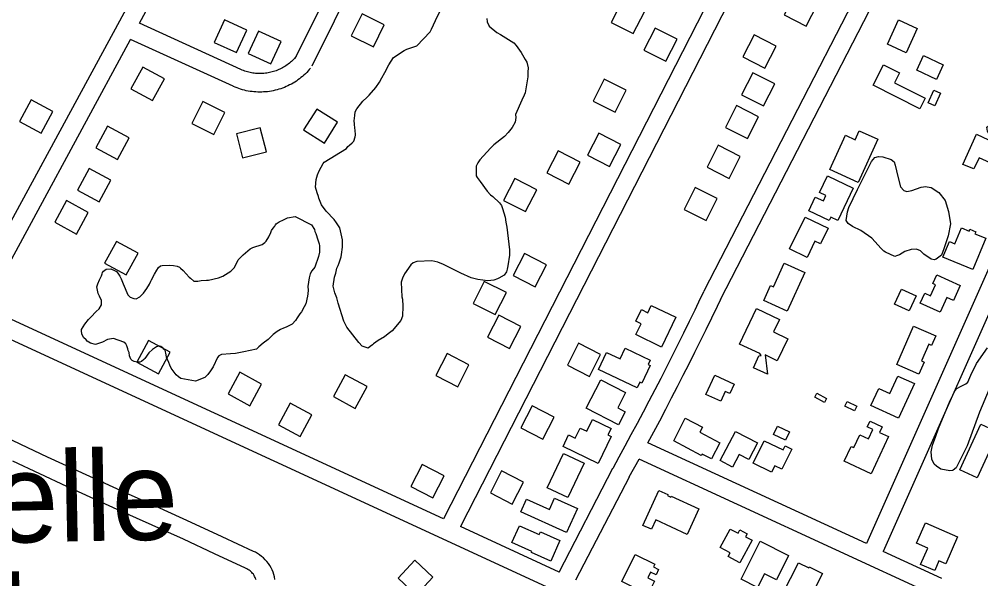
# Model space of a CAD drawing. Extents: x 3683402 to 3721514, y 487807 to 513565.
# Drawn here: x 3705384 to 3706941, y 494703 to 495610 of the extents above; entities that cross this region are included whole.
import ezdxf

# ---------------------------------------------------------------- set-up
doc = ezdxf.new("R2010")
doc.units = 0
for name, color, linetype in [('V-BLDG-OTLN', 7, 'Continuous'), ('V-ROAD-CNTR', 7, 'Continuous'), ('V-SITE-VEGE', 7, 'Continuous'), ('V-TOPO-GNAM-IDEN', 7, 'Continuous')]:
    doc.layers.add(name, color=color, linetype=linetype)

msp = doc.modelspace()

# ---------------------------------------------------------------- linework, layer by layer
at = {"layer": 'V-BLDG-OTLN'}
for points in [[(3706378.4, 495586.3), (3706396.6, 495621.9), (3706361, 495640.1), (3706342.8, 495604.5)], [(3706658.5, 495598.4), (3706676.6, 495634.1), (3706641, 495652.2), (3706622.8, 495616.6)], [(3705699.6, 495572.2), (3705736, 495555.6), (3705752.6, 495591.9), (3705716.3, 495608.6)], [(3705939.4, 495618.6), (3705921.6, 495582.7), (3705957.5, 495565), (3705975.2, 495600.8)], [(3706838.3, 495594.8), (3706820.2, 495555.3), (3706790, 495569.1), (3706808.1, 495608.6)], [(3706431.1, 495541.6), (3706449.3, 495577.2), (3706413.7, 495595.4), (3706395.5, 495559.8)], [(3705755, 495553.9), (3705791.4, 495537.3), (3705808, 495573.7), (3705771.7, 495590.3)], [(3706591.5, 495530.6), (3706609.7, 495566.3), (3706574, 495584.4), (3706555.9, 495548.7)], [(3706837.6, 495527.1), (3706848.6, 495550.8), (3706880.6, 495535.9), (3706869.6, 495512.2)], [(3705584, 495532.2), (3705564.9, 495497), (3705600.1, 495477.9), (3705619.2, 495513.1)], [(3706801.5, 495506.8), (3706851.1, 495481.7), (3706842.5, 495464.7), (3706767.1, 495502.8), (3706783.8, 495535.8), (3706809.5, 495522.7)], [(3706589.4, 495469.1), (3706607.6, 495504.8), (3706571.9, 495522.9), (3706553.8, 495487.3)], [(3706348.9, 495458.9), (3706367.1, 495494.5), (3706331.5, 495512.7), (3706313.3, 495477.1)], [(3706856.1, 495474), (3706865.3, 495494.5), (3706875.9, 495489.7), (3706866.7, 495469.3)], [(3705419.4, 495424.9), (3705438.5, 495460), (3705403.3, 495479.1), (3705384.3, 495443.9)], [(3705663.5, 495440.5), (3705699.4, 495422.8), (3705717.1, 495458.6), (3705681.3, 495476.3)], [(3706563.4, 495416.2), (3706581.5, 495451.8), (3706545.9, 495470), (3706527.7, 495434.3)], [(3705878.3, 495408.9), (3705899.7, 495442.7), (3705865.9, 495464.1), (3705844.5, 495430.3)], [(3706912, 495374.5), (3706934.3, 495423.2), (3706953.9, 495414.2), (3706958.1, 495423.2), (3706955.1, 495423.9), (3706952.1, 495428.2), (3706951.2, 495434.8), (3706956.3, 495439.1), (3706962.9, 495439), (3706964.2, 495438.2), (3706976.5, 495466.2), (3707016.6, 495448.1), (3706991.5, 495396.4), (3706982.1, 495400.9), (3706969.3, 495371.1), (3706938.5, 495385.3), (3706929.9, 495367.1)], [(3705526.9, 495436.4), (3705507.8, 495401.3), (3705542.9, 495382.2), (3705562, 495417.3)], [(3705745.5, 495385), (3705784.3, 495394.9), (3705774.4, 495433.6), (3705735.7, 495423.8)], [(3706340.2, 495371.1), (3706358.4, 495406.7), (3706322.8, 495424.9), (3706304.6, 495389.3)], [(3706696.9, 495366), (3706722.1, 495421.7), (3706738, 495414.5), (3706744.5, 495428.8), (3706774.4, 495415.3), (3706742.8, 495345.3)], [(3706274.1, 495342.3), (3706292.3, 495378), (3706256.7, 495396.2), (3706238.5, 495360.6)], [(3706533.7, 495351.7), (3706551.8, 495387.4), (3706516.2, 495405.5), (3706498, 495369.8)], [(3705497.3, 495367.9), (3705478.3, 495332.8), (3705513.4, 495313.7), (3705532.5, 495348.9)], [(3706203.9, 495297.9), (3706222.1, 495333.5), (3706186.5, 495351.7), (3706168.2, 495316.1)], [(3706695.9, 495283.6), (3706662.6, 495299.3), (3706673.2, 495321.6), (3706686.3, 495315.4), (3706690.3, 495323.9), (3706680, 495328.7), (3706692.8, 495355.8), (3706734.4, 495336.2), (3706709.6, 495283.6), (3706698.4, 495288.9)], [(3706496.4, 495283.3), (3706514.5, 495319), (3706478.9, 495337.1), (3706460.8, 495301.4)], [(3705460.5, 495315.8), (3705441.4, 495280.6), (3705476.6, 495261.6), (3705495.6, 495296.7)], [(3706659.9, 495223.8), (3706631.7, 495237.4), (3706656.7, 495289.2), (3706693.9, 495271.3), (3706681.5, 495245.6), (3706672.5, 495249.9)], [(3706899.4, 495245.6), (3706910.2, 495271.6), (3706922.5, 495266.5), (3706923.6, 495269.3), (3706933, 495265.4), (3706931.7, 495262.2), (3706949.6, 495254.7), (3706928.6, 495204.2), (3706880, 495224.3), (3706890.4, 495249.3)], [(3705541.3, 495249.6), (3705522.2, 495214.5), (3705557.4, 495195.4), (3705576.4, 495230.6)], [(3706219.5, 495176.1), (3706237.7, 495211.7), (3706202.1, 495229.9), (3706183.9, 495194.3)], [(3706656.3, 495199.2), (3706627.9, 495136.7), (3706590, 495153.9), (3706600.9, 495178), (3706605.5, 495176), (3706622.9, 495214.3)], [(3706870, 495195.7), (3706908.1, 495178.4), (3706896.9, 495153.9), (3706886.4, 495158.7), (3706875.5, 495134.8), (3706843.2, 495149.4), (3706850.7, 495165.8), (3706859.7, 495161.7), (3706867.7, 495179.3), (3706863.4, 495181.3)], [(3706154.7, 495131.1), (3706172.9, 495166.7), (3706137.2, 495184.9), (3706119, 495149.3)], [(3706836.5, 495161.7), (3706825.5, 495137.2), (3706801.6, 495148), (3706812.7, 495172.5)], [(3706407.5, 495146), (3706447.4, 495126.7), (3706424, 495078.5), (3706382.6, 495098.6), (3706391.3, 495116.4), (3706382.8, 495120.5), (3706391.8, 495139.1), (3706401.8, 495134.2)], [(3706550.3, 495083.3), (3706578, 495141), (3706615.1, 495123.1), (3706605.6, 495103.2), (3706628.8, 495092), (3706611.6, 495056.3), (3706592.1, 495065.7), (3706595.7, 495034.6), (3706573, 495044.6), (3706581.7, 495064.3), (3706585.5, 495064.7), (3706583.5, 495067.8)], [(3706178.1, 495076.4), (3706196.3, 495112), (3706160.7, 495130.2), (3706142.5, 495094.6)], [(3706805.2, 495050.3), (3706832.3, 495112.3), (3706868.5, 495096.5), (3706861.7, 495081), (3706857.1, 495083), (3706845.4, 495056.1), (3706849.7, 495054.2), (3706841.1, 495034.6)], [(3705593.2, 495089.3), (3705574.2, 495054.1), (3705609.3, 495035.1), (3705628.4, 495070.2)], [(3706290, 495084.6), (3706271.8, 495049), (3706307.4, 495030.8), (3706325.6, 495066.4)], [(3706094.2, 495014.2), (3706112.4, 495049.8), (3706076.8, 495068), (3706058.6, 495032.4)], [(3706384.7, 495012.6), (3706322.3, 495042.2), (3706335.3, 495069.6), (3706357.1, 495059.2), (3706365.5, 495076.8), (3706406, 495057.5), (3706402.5, 495050.2), (3706405.8, 495048.6), (3706392.4, 495020.2), (3706389, 495021.7)], [(3705741.3, 495037.7), (3705722.3, 495002.5), (3705757.4, 494983.5), (3705776.5, 495018.6)], [(3705912.1, 495033.4), (3705893.1, 494998.3), (3705928.2, 494979.2), (3705947.3, 495014.4)], [(3706496.2, 495001.8), (3706510.6, 495032.8), (3706541.8, 495018.3), (3706534.7, 495003), (3706527.5, 495006.3), (3706520.2, 494990.7)], [(3706354.6, 494952.6), (3706302.4, 494979.4), (3706326, 495025.4), (3706366, 495004.8), (3706353.2, 494979.9), (3706365.4, 494973.6)], [(3706833.7, 495019.5), (3706808, 494963.5), (3706763.4, 494984), (3706776.1, 495011.6), (3706794.2, 495003.2), (3706807.2, 495031.6)], [(3706675.9, 495003.8), (3706691.5, 494995.2), (3706687.9, 494988.7), (3706672.3, 494997.3)], [(3705822.8, 494987.8), (3705803.7, 494952.6), (3705838.9, 494933.5), (3705858, 494968.7)], [(3706736.9, 494975), (3706721, 494982.6), (3706724.7, 494990.3), (3706740.6, 494982.7)], [(3706214.7, 494983.2), (3706196.4, 494947.6), (3706232.1, 494929.4), (3706250.3, 494965)], [(3706321.7, 494890), (3706264.7, 494917.4), (3706273.7, 494936.1), (3706284.4, 494931), (3706292.2, 494947.3), (3706303.1, 494942), (3706312.3, 494961.2), (3706342.5, 494946.7), (3706337.5, 494936.3), (3706342.7, 494933.7)], [(3706443.9, 494926.4), (3706462.6, 494963.2), (3706490.4, 494948.5), (3706486.2, 494940.6), (3706518.9, 494923.1), (3706505.1, 494897.2), (3706490.1, 494905.2), (3706488.6, 494902.9)], [(3706763.6, 494873.3), (3706720, 494893.8), (3706731.1, 494917.6), (3706735.6, 494915.5), (3706745.3, 494936.2), (3706759.2, 494929.7), (3706766.3, 494944.8), (3706757.4, 494949), (3706761.9, 494958.5), (3706781.6, 494949.2), (3706777.4, 494940.2), (3706791.7, 494933.4)], [(3706543.8, 494941.8), (3706579.5, 494923.2), (3706565.5, 494896.1), (3706549.8, 494904.3), (3706539.3, 494884.1), (3706519.3, 494894.5)], [(3706631.3, 494941), (3706624.8, 494927.6), (3706605.6, 494937), (3706612.1, 494950.4)], [(3706969.5, 494940.8), (3706935.5, 494866.6), (3706907.5, 494879.4), (3706941.5, 494953.6)], [(3706572.7, 494890.3), (3706590.3, 494926.6), (3706621, 494911.8), (3706624.2, 494918.4), (3706635, 494913.2), (3706619.3, 494880.6), (3706607.6, 494886.2), (3706602.6, 494875.9)], [(3706239.2, 494850.5), (3706265.6, 494905.9), (3706298.8, 494890.2), (3706272.4, 494834.8)], [(3706053.8, 494834.1), (3706072, 494869.8), (3706036.4, 494888), (3706018.2, 494852.4)], [(3706165.2, 494877.7), (3706147, 494842.1), (3706182.6, 494823.9), (3706200.8, 494859.5)], [(3706484.8, 494816.4), (3706466, 494775), (3706414.8, 494798.3), (3706407.9, 494783.2), (3706394.1, 494789.4), (3706420, 494846.2), (3706434.5, 494839.6), (3706433.7, 494838), (3706439.4, 494835.4), (3706440.1, 494836.8)], [(3706288, 494816.7), (3706270.5, 494777.9), (3706196.4, 494811.3), (3706205.7, 494832), (3706242.8, 494815.3), (3706251, 494833.4)], [(3706259.6, 494765.3), (3706244.8, 494731.6), (3706213.5, 494745.4), (3706214.4, 494747.5), (3706182, 494761.8), (3706194, 494788.9), (3706226.1, 494774.8), (3706228, 494779.2)], [(3706551.3, 494728.9), (3706532.4, 494739.1), (3706535.6, 494745.1), (3706519.3, 494753.9), (3706535.4, 494783.7), (3706548.3, 494776.7), (3706551.3, 494782.1), (3706562.9, 494775.9), (3706560.4, 494771.2), (3706571, 494765.5)], [(3706851.6, 494793.8), (3706903.8, 494771.1), (3706884.6, 494727.1), (3706873.4, 494732), (3706866.6, 494716.3), (3706843.7, 494726.3), (3706855.3, 494752.9), (3706837.2, 494760.8)], [(3706553, 494702.3), (3706583.9, 494763.9), (3706629.9, 494740.8), (3706610.2, 494701.5), (3706591.1, 494711.1), (3706579.9, 494688.8)], [(3706402.2, 494677.7), (3706360, 494698.4), (3706381.6, 494742.3), (3706413.2, 494726.8), (3706411, 494722.2), (3706419.5, 494718.1), (3706415.3, 494709.5), (3706406.5, 494713.8), (3706402, 494704.6), (3706412.8, 494699.3)], [(3705997.5, 494703.9), (3706026.7, 494676.5), (3706054.1, 494705.6), (3706024.9, 494733)], [(3706619.9, 494677.9), (3706645.9, 494729.1), (3706662.8, 494720.6), (3706663.6, 494722.3), (3706684.9, 494711.5), (3706668.9, 494680), (3706688, 494670.3), (3706674, 494642.7), (3706671.1, 494644.2), (3706660, 494622.4), (3706637.3, 494634), (3706645.6, 494650.2), (3706629.1, 494658.5), (3706635.1, 494670.2)]]:
    msp.add_lwpolyline(points, close=True, dxfattribs=at)
at = {"layer": 'V-ROAD-CNTR'}
for p, q in [((3706245.1, 494687), (3705041.7, 495241.7)), ((3706756, 494760.1), (3706402.3, 494923.5)), ((3706371.9, 494868), (3706388, 494897.1)), ((3706865.6, 494676.4), (3706388, 494897.1))]:
    msp.add_line(p, q, dxfattribs=at)
for points in [[(3706968.2, 496488.5), (3706098.6, 494787.6)], [(3705578.6, 495603.3), (3705995.5, 496372)], [(3706194, 496279), (3705830.8, 495546.7)], [(3706221.1, 496266.3), (3705857.7, 495533.4)], [(3706704.9, 496039.5), (3706071.3, 494800.2)], [(3705301.4, 495155), (3705771.6, 496022.1)], [(3706493.3, 495169.4), (3706885.5, 495931.7), (3706914.8, 495986.3)], [(3706520, 495155.7), (3706912, 495917.8), (3706941.2, 495972.1)], [(3705742.7, 495528.3), (3705578.6, 495603.3)], [(3705328.7, 495142.4), (3705564.3, 495576.9)], [(3705730.3, 495501), (3705564.3, 495576.9)], [(3705832.7, 495549.7), (3705831.1, 495547.8), (3705829.7, 495546.1), (3705828.1, 495544.5), (3705826.5, 495542.9), (3705824.9, 495541.4), (3705823.2, 495539.9), (3705821.5, 495538.4), (3705819.7, 495537.1), (3705817.9, 495535.7), (3705816, 495534.4), (3705814.1, 495533.2), (3705812.2, 495532), (3705810.3, 495530.9), (3705808.3, 495529.9), (3705806.3, 495528.9), (3705804.2, 495528), (3705802.1, 495527.1), (3705800, 495526.3), (3705797.9, 495525.5), (3705795.8, 495524.8), (3705793.6, 495524.2), (3705791.4, 495523.7), (3705789.3, 495523.2), (3705787, 495522.8), (3705784.8, 495522.4), (3705782.6, 495522.1), (3705780.4, 495521.9), (3705778.1, 495521.7), (3705775.9, 495521.6), (3705773.6, 495521.6), (3705771.4, 495521.6), (3705769.1, 495521.7), (3705766.9, 495521.9), (3705764.6, 495522.2), (3705762.4, 495522.5), (3705760.2, 495522.8), (3705758, 495523.3), (3705755.8, 495523.8), (3705753.6, 495524.3), (3705751.5, 495525), (3705749.3, 495525.7), (3705747.2, 495526.4), (3705745.1, 495527.3), (3705743, 495528.2), (3705742.6, 495528.3)], [(3705855.7, 495530.4), (3705853.8, 495528.2), (3705851.8, 495525.9), (3705849.6, 495523.6), (3705847.4, 495521.4), (3705845.1, 495519.2), (3705842.7, 495517.1), (3705840.3, 495515.1), (3705837.9, 495513.2), (3705835.3, 495511.3), (3705832.8, 495509.5), (3705830.1, 495507.8), (3705827.4, 495506.2), (3705824.7, 495504.6), (3705821.9, 495503.2), (3705819.1, 495501.8), (3705816.3, 495500.5), (3705813.4, 495499.3), (3705810.4, 495498.1), (3705807.5, 495497.1), (3705804.5, 495496.1), (3705801.5, 495495.3), (3705798.4, 495494.5), (3705795.4, 495493.8), (3705792.3, 495493.2), (3705789.2, 495492.7), (3705786.1, 495492.3), (3705782.9, 495492), (3705779.8, 495491.8), (3705776.7, 495491.6), (3705773.5, 495491.6), (3705770.4, 495491.7), (3705767.3, 495491.8), (3705764.1, 495492), (3705761, 495492.4), (3705757.9, 495492.8), (3705754.8, 495493.3), (3705751.7, 495493.9), (3705748.7, 495494.6), (3705745.6, 495495.4), (3705742.6, 495496.3), (3705739.6, 495497.3), (3705736.7, 495498.3), (3705733.7, 495499.5), (3705730.9, 495500.7), (3705730.4, 495501)], [(3706998.2, 495304.8), (3706756, 494760.1)], [(3707025.6, 495292.6), (3706783.2, 494747.5)], [(3706345.7, 494882.5), (3706355.6, 494900.6), (3706365.5, 494918.7), (3706375.3, 494936.9), (3706385.1, 494955), (3706394.8, 494973.3), (3706404.4, 494991.5), (3706413.9, 495009.8), (3706423.4, 495028.2), (3706432.8, 495046.5), (3706442.1, 495064.9), (3706451.3, 495083.4), (3706460.5, 495101.8), (3706469.6, 495120.4), (3706478.7, 495138.9), (3706487.6, 495157.5), (3706493.1, 495169)], [(3706071.3, 494800.2), (3705328.7, 495142.4)], [(3706402.3, 494923.5), (3706421.3, 494959.2), (3706431, 494977.6), (3706440.5, 494996), (3706450.1, 495014.4), (3706459.5, 495032.9), (3706468.9, 495051.4), (3706478.2, 495070), (3706487.4, 495088.5), (3706496.6, 495107.2), (3706505.7, 495125.8), (3706514.7, 495144.5), (3706520.2, 495156.1)], [(3705798, 494702.1), (3705797.3, 494706), (3705796.3, 494709.9), (3705795, 494713.7), (3705793.5, 494717.4), (3705791.8, 494721), (3705789.8, 494724.5), (3705787.6, 494727.8), (3705785.1, 494731), (3705782.4, 494734), (3705779.6, 494736.8), (3705776.6, 494739.4), (3705773.3, 494741.8), (3705770, 494744), (3705766.5, 494745.9), (3705763.3, 494747.4), (3705712.9, 494770.9), (3705662.3, 494794.3), (3705611.6, 494817.3), (3705560.9, 494840.1), (3705517.2, 494859.9), (3705473.5, 494879.9), (3705430, 494900.1), (3705386.5, 494920.5), (3705343.2, 494941)], [(3705767.5, 494701.4), (3705766.9, 494703.3), (3705766.1, 494705.1), (3705765.3, 494706.9), (3705764.3, 494708.6), (3705763.2, 494710.3), (3705762, 494711.8), (3705760.7, 494713.3), (3705759.3, 494714.7), (3705757.8, 494716), (3705756.2, 494717.1), (3705754.5, 494718.2), (3705752.8, 494719.2), (3705750.6, 494720.2), (3705700.2, 494743.7), (3705649.8, 494767), (3705599.3, 494790), (3705548.6, 494812.8), (3705504.7, 494832.6), (3705461, 494852.7), (3705417.3, 494872.9), (3705373.7, 494893.4)], [(3706258.3, 494713.9), (3706345.5, 494882.2)], [(3706285.6, 494701.4), (3706372.1, 494868.4)], [(3706258.3, 494713.9), (3706098.6, 494787.6)], [(3706878.2, 494703.6), (3706783.2, 494747.5)]]:
    msp.add_lwpolyline(points, dxfattribs=at)
at = {"layer": 'V-SITE-VEGE'}
for points in [[(3705918.9, 495405.8), (3705923.4, 495409.3), (3705925.9, 495411.9), (3705928.3, 495418.9), (3705928.8, 495421.9), (3705928.3, 495430.5), (3705927.7, 495432.5), (3705927.2, 495440), (3705926.7, 495445), (3705927.6, 495453.6), (3705928.1, 495459.6), (3705930.6, 495464.7), (3705940.5, 495476.8), (3705947, 495482.9), (3705950.5, 495486.4), (3705961.5, 495499), (3705967.5, 495507.6), (3705971, 495514.7), (3705976, 495523.3), (3705982.4, 495535.9), (3705989.9, 495547.5), (3706007.4, 495559.1), (3706011.9, 495561.2), (3706028, 495566.8), (3706049.5, 495589.1), (3706051.9, 495593.6), (3706057.9, 495607.7), (3706066.8, 495625.4)], [(3706141.3, 495610.7), (3706141.8, 495605.7), (3706144.9, 495598.7), (3706157.5, 495588.2), (3706163.6, 495584.7), (3706184.8, 495571.3), (3706188.8, 495567.3), (3706196.9, 495555.8), (3706203.5, 495544.2)], [(3706203.5, 495544.2), (3706206.1, 495540.2), (3706208.2, 495530.7), (3706207.7, 495523.7), (3706207.7, 495516.6), (3706203.4, 495490.5), (3706201.9, 495486.4), (3706197.9, 495478.4), (3706188, 495455.2), (3706188.5, 495450.2), (3706187.1, 495443.1), (3706182.1, 495434.5), (3706175.6, 495425.9), (3706170.1, 495419.9), (3706152.6, 495406.2), (3706147.1, 495400.6), (3706130.1, 495381.9), (3706126.6, 495376.9), (3706124.2, 495371.8), (3706123.8, 495355.8), (3706125.8, 495353.3), (3706130.3, 495346.7), (3706142, 495331.2), (3706147.1, 495325.2), (3706151.1, 495322.2), (3706161.7, 495312.3), (3706165.3, 495307.8), (3706166.8, 495303.2), (3706170.9, 495289.2), (3706172, 495281.1), (3706173.5, 495272.6), (3706177.8, 495235.9), (3706177.8, 495227.4), (3706175.4, 495210.3), (3706174.4, 495204.8), (3706173, 495200.2), (3706169.5, 495195.2), (3706161, 495190.1), (3706158.5, 495189.1), (3706152.4, 495187), (3706142.9, 495186), (3706126.8, 495187.9), (3706115.7, 495190.8), (3706099.1, 495198.3), (3706071.3, 495212.2), (3706061.8, 495216.1), (3706052.2, 495218.1), (3706028.1, 495216.9), (3706022.1, 495214.9), (3706018.1, 495211.8), (3706008.1, 495197.2), (3706004.6, 495190.1), (3706002.7, 495183.6), (3706003.8, 495160), (3706004.8, 495156), (3706005.4, 495144.9), (3706004.5, 495128.3), (3706002, 495121.8), (3705988.1, 495104.6), (3705981.5, 495100), (3705975.5, 495095), (3705965.5, 495088.9), (3705958, 495083.8), (3705956, 495082.3), (3705952.5, 495079.2), (3705949, 495076.7), (3705939.4, 495080.2), (3705933.9, 495085.7), (3705914.6, 495110.7), (3705909.5, 495120.7), (3705900.3, 495149.8), (3705898.2, 495158.3), (3705895.2, 495166.4), (3705892.6, 495176.9), (3705894.5, 495191.5), (3705896.5, 495198), (3705898.5, 495206.1), (3705900.4, 495210.6), (3705901.9, 495215.2), (3705904.4, 495221.2), (3705905.4, 495224.7), (3705905.9, 495228.3), (3705907.8, 495240.3), (3705907.7, 495252.4), (3705903.1, 495271.5), (3705898, 495280), (3705894, 495285), (3705881.3, 495298.5), (3705873.7, 495309), (3705869.1, 495320), (3705868.6, 495322.5), (3705866.5, 495328.6), (3705864, 495337.6), (3705864.9, 495350.2), (3705866.9, 495357.7), (3705869.9, 495363.8), (3705876.3, 495375.9), (3705877.8, 495377.9), (3705913.9, 495400.2), (3705916.4, 495403.3), (3705918.9, 495405.8)], [(3705570.3, 495055.1), (3705566.8, 495056.7), (3705564.9, 495058.7), (3705562.4, 495064.3), (3705562, 495069.8), (3705560.5, 495072.9), (3705560.1, 495075.4), (3705558.1, 495080.5), (3705556.7, 495083.5), (3705553.2, 495086.6), (3705536.7, 495092.3), (3705533.7, 495091.9), (3705527.1, 495090.5), (3705519, 495086.6), (3705507.4, 495082.7), (3705499.4, 495084.8), (3705493.9, 495087.9), (3705492.4, 495090), (3705488, 495094.1), (3705485.5, 495100.1), (3705484.6, 495104.7), (3705485.1, 495106.7), (3705490.3, 495115.6), (3705496.4, 495123.1), (3705500, 495127.1), (3705508.7, 495136), (3705513.3, 495140.4), (3705517.4, 495146.9), (3705517, 495154.5), (3705515, 495158.5), (3705514.1, 495161), (3705511.6, 495165.1), (3705509.8, 495176.2), (3705511.3, 495181.2), (3705513.9, 495187.2), (3705517.1, 495193.7), (3705518.1, 495197.2), (3705519.1, 495199.2), (3705520.7, 495201.7), (3705524.8, 495204.6), (3705532.3, 495205), (3705538.3, 495202.4), (3705541.3, 495200.9), (3705543.8, 495198.3), (3705547.2, 495193.2), (3705549.2, 495189.2), (3705552.6, 495181.1), (3705559.8, 495162.9), (3705563.8, 495159.3), (3705569.8, 495157.2), (3705573.3, 495156.7), (3705579.4, 495160.1), (3705583, 495163.6), (3705585, 495166), (3705590.7, 495173.5), (3705594.8, 495180.5), (3705597.4, 495185), (3705598.4, 495187.5), (3705603.1, 495196.4), (3705606.7, 495202.9), (3705609.8, 495207.4), (3705612.8, 495209.9), (3705615.3, 495210.8), (3705627.9, 495211.2), (3705633.9, 495210.6), (3705640, 495209.5), (3705643.5, 495207.9), (3705645.4, 495206.4), (3705649.4, 495202.3), (3705659.3, 495191.6), (3705661.3, 495190.1), (3705666.8, 495185.5), (3705673.3, 495185.4), (3705678.8, 495186.3), (3705687.4, 495186.7), (3705690.4, 495187.1), (3705706.6, 495190.9), (3705713.6, 495193.3), (3705718.2, 495196.3), (3705726.8, 495201.2), (3705730.9, 495205.6), (3705732.9, 495207.6), (3705738.6, 495219.6), (3705740.7, 495222.1), (3705746.8, 495228), (3705758, 495237.9), (3705762.6, 495239.9), (3705777.7, 495244.7), (3705781.8, 495248.1), (3705783.8, 495250.1), (3705788.5, 495257.1), (3705791.6, 495264.1), (3705792.6, 495267.1), (3705795.2, 495271.1), (3705797.8, 495274.5), (3705798.8, 495276.5), (3705800.3, 495278), (3705804.9, 495281.5), (3705812, 495284.9), (3705818.6, 495287.8), (3705830.7, 495290.2)], [(3705830.7, 495290.2), (3705857.1, 495276.7), (3705862, 495269.1), (3705863, 495265.6), (3705864.4, 495262.5), (3705867.8, 495252.4), (3705869.7, 495245.8), (3705870.2, 495242.3), (3705870.1, 495238.3), (3705870.5, 495232.3), (3705868.9, 495225.2), (3705862.6, 495207.7), (3705858, 495201.8), (3705855, 495197.3), (3705853.3, 495190.8), (3705851.6, 495176.7), (3705852, 495170.7), (3705851.5, 495164.7), (3705850.9, 495161.2), (3705848.2, 495148.6), (3705845.6, 495143.6), (3705841, 495135.7), (3705838.4, 495132.2), (3705834.3, 495125.7), (3705831.2, 495121.7), (3705826.1, 495115.8), (3705816.5, 495110.9), (3705811.9, 495108.9), (3705806.9, 495107), (3705801.8, 495103.6), (3705795.2, 495098.6), (3705787, 495090.7), (3705778.9, 495084.8), (3705771.8, 495078.9), (3705768.2, 495074.9), (3705747.5, 495070.7), (3705734.4, 495068.3), (3705726.4, 495067.5), (3705711.8, 495066.7), (3705707.2, 495064.2), (3705705.2, 495061.7), (3705697.9, 495046.3), (3705693.8, 495039.8), (3705689.7, 495034.3), (3705684.6, 495029.4), (3705669.4, 495023), (3705645.9, 495027.4), (3705641.9, 495030), (3705637.9, 495033.5), (3705630, 495044.2), (3705628.1, 495049.3), (3705626.1, 495053.3), (3705622.7, 495061.9), (3705621.8, 495066), (3705620.4, 495073.5), (3705618.4, 495075.1), (3705616.4, 495077.1), (3705613.4, 495079.2), (3705611.4, 495079.7), (3705606.4, 495078.8), (3705599.8, 495074.8), (3705593.7, 495068.9), (3705587.5, 495059.9), (3705586, 495058.4), (3705581.9, 495055), (3705579.4, 495054), (3705574.9, 495054.1), (3705570.3, 495055.1)], [(3706966.2, 495037.2), (3706939, 494972.9), (3706919, 494918.2), (3706901.6, 494882.8), (3706896.4, 494878.9), (3706895.6, 494878.6), (3706890.9, 494878.2), (3706876.4, 494880.8), (3706869.4, 494885.6), (3706866, 494888.8), (3706862.2, 494897.1), (3706860.8, 494908.5), (3706863.3, 494919.4), (3706868.6, 494934.3), (3706872.7, 494946.8), (3706891.8, 494992), (3706899.9, 495008.3), (3706902.3, 495011.1), (3706908.6, 495014.5), (3706917.3, 495019.1), (3706920.1, 495021.8), (3706924.9, 495032.7), (3706934.3, 495051.8), (3706951.9, 495077.4)]]:
    msp.add_lwpolyline(points, dxfattribs=at)
msp.add_lwpolyline([(3706801.9, 495225.2), (3706786.7, 495232.1), (3706784, 495234.1), (3706780.1, 495238.4), (3706764.7, 495255.1), (3706747.2, 495267.5), (3706733.6, 495273.6), (3706726.6, 495278.8), (3706723.2, 495283.6), (3706725.3, 495297.6), (3706727.4, 495304.7), (3706741.5, 495333.8), (3706764.1, 495379.3), (3706769.7, 495385.5), (3706775.6, 495387.4), (3706782.7, 495386.5), (3706795.9, 495382.4), (3706801, 495378.4), (3706802.8, 495373.3), (3706806.9, 495354.8), (3706811.3, 495338.3), (3706816.4, 495332.3), (3706821.4, 495330.3), (3706829.7, 495332.1), (3706844.6, 495337.8), (3706852.1, 495338.9), (3706854.4, 495338.1), (3706860.7, 495336.8), (3706873.1, 495329.2), (3706883.5, 495316.1), (3706889.1, 495298), (3706892, 495278), (3706888.5, 495258.8), (3706881.6, 495237.4), (3706877.5, 495227.6), (3706868.8, 495220.7), (3706866, 495219.6), (3706861, 495220.8), (3706848.9, 495228.8), (3706843.5, 495234.4), (3706836.9, 495237.2), (3706828.3, 495236.6), (3706818, 495233.2), (3706809.7, 495228.2), (3706805, 495226.3)], close=True, dxfattribs=at)

# ---------------------------------------------------------------- texts
at = {"layer": 'V-TOPO-GNAM-IDEN'}
for s, p in [('Belle', (3705211.6, 494758.4)), ('Chasse', (3705216.2, 494559.1))]:
    msp.add_text(s, height=145, rotation=1.1486, dxfattribs=at).set_placement(p)

doc.saveas('drawing.dxf')
